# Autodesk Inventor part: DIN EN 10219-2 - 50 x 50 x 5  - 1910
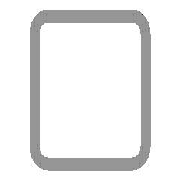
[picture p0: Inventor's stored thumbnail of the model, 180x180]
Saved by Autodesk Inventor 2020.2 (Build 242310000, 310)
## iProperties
IsCustomPart: 1
_CCFamilyMember: 16
_CCFamilyDisplayName: DIN EN 10219-2 (Quadratisches Hohlprofil - Kaltgeformt) - Kaltgeformte, geschweißte Baustahl-Hohlprofile aus unlegiertem Feinkorn-Baustahl
_FrameMemberDoc: Frame Member File
_Version: 15.0.0
_GetPNFromCC: 1
Created: 2019-01
Part Number: DIN EN 10219-2 - 50 x 50 x 5  - 1910
Material: Stahl, weich
Description: Kaltgeformte, geschweißte Baustahl-Hohlprofile aus unlegiertem Feinkorn-Baustahl
Document SubType Name: Modeling
Standard: DIN
Designer: lutzd
Standard Revision: 2006-07
Standards Organization: DIN
Language: de-DE
Size Designation: 50 x 50 x 5
Categories: <MemberInstance><Categories><Category DisplayName="Profile" InternalName="089c4875-fa83-4c05-b084-43b9cc11f5ed" Mnemonic="GRDR"><CategoryParameter DisplayName="
Stock Number: 50 x 50 x 5
Mass: 12515.2 g
Surface Area: 6404.35 cm^2
Volume: 1594.3 cm^3
Density: 7.85 g/cm^3
Appearance: Semi-Polished(8)
G_L: 1910,000 mm
G_W: 50,000 mm
G_H: 50,000 mm
DocNumber: ADSK-014383
Folder: .
Mass: 12,515 kg
VLT_Material: Stahl, weich
+C44415D3-DE04-4AD7-8A43-A2E09D2D25DA+SCHNITTDETAIL1: Schnittwinkel 90,00 grd
+0C2ABF72-8B65-4217-8014-3100D4A5692D+SCHNITTDETAIL2: Schnittwinkel 90,00 grd
Dimensions: 50x50x1910 mm
Title: Profil-Bauteil
Author: lutzd
Revision Number: -
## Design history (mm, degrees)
node "Startebene"
node "Endebene"
sketch "Skizze"
  geometry: L1 (-25, -15)-(-25, 15); L2 (-15, 25)-(15, 25); L3 (25, 15)-(25, -15); L4 (15, -25)-(-15, -25); L5 (-15, 20)-(15, 20); L6 (20, 15)-(20, -15); L7 (15, -20)-(-15, -20); L8 (-20, -15)-(-20, 15); L9 (0, 37.899)-(0, -37.899) reference; L10 (-37.899, 0)-(37.899, 0) reference; A1 r 10 centre (-15, -15) between (-25, -15) and (-15, -25); A2 r 10 centre (-15, 15) between (-15, 25) and (-25, 15); A3 r 10 centre (15, 15) between (25, 15) and (15, 25); A4 r 10 centre (15, -15) between (15, -25) and (25, -15); A5 r 5 centre (-15, 15) between (-15, 20) and (-20, 15); A6 r 5 centre (15, 15) between (20, 15) and (15, 20); A7 r 5 centre (15, -15) between (15, -20) and (20, -15); A8 r 5 centre (-15, -15) between (-20, -15) and (-15, -20)
  constraints: 16 end point, 16 point on circle, 8 centre point, 8 tangent, 4 parallel, 3 equal radius, 2 perpendicular, 7 other
  dimensions: "d7" = 10 radius of A1 (= G_IR); "d10" = 50 distance between parallel lines of L2 L4 (= G_H); "d11" = 50 distance between parallel lines of L1 L3 (= G_W); "d12" = 5 distance between parallel lines of L3 L6 (= G_T); "d15" = 25 distance between parallel lines of L2 L10 (= 0.5 x d10); "d16" = 25 distance between parallel lines of L9 L3 (= 0.5 x d11)
extrude "Körper" new body sketch "Skizze" stored distance "d3" = 1910 (= G_L); taper "d4" = 0 deg
node "Driven Length"
  sketch "Sketch3"
    geometry: L1 (0, 0)-(10, 0) reference
    constraints: 2 end point, 1 horizontal
  workplane "Work Plane3"
  sketch "Sketch4"
    geometry: L1 (-2, 50)-(12, 50) reference; L2 (-2, 1960)-(12, 1960) reference
    dimensions: "d18" = 1910 distance between parallel lines of L1 L2 (derived)
workplane "Arbeitsebene4"
feature "Trennen1"
workplane "Arbeitsebene5"
feature "Trennen2"
sketch "Skizze5"
  geometry: L1 (30, 0)-(0, 0) reference; L2 (15, 0)-(15, 200); 3 further points
  constraints: 4 end point, 1 coincident, 1 horizontal, 1 midpoint, 1 point on line, 1 vertical, 2 other
  dimensions: "d19" = 70 distance of point (15, 130) point (15, 200); "d20" = 200 distance of L2.start L2.end
hole "Bohrung1" sketch "Skizze5" at (15, 200), (15, 130) diameter "d21" = 6.647; stored, may be unused: countersink angle "d25" = 90 deg, drill point angle "d27" = 118 deg; dims "d22" = 16, "d23" = 4, "d24" = 2, "d26" = 8
sketch "Skizze6"
  geometry: L1 (0, 1910)-(-30, 1910) reference; L2 (-15, 1910)-(-15, 532); 5 further points
  constraints: 4 end point, 3 point on line, 1 coincident, 1 horizontal, 1 midpoint, 1 vertical, 2 other
  dimensions: "d28" = 90 distance of point (-15, 1395.5) point (-15, 1485.5); "d29" = 424.5 distance from line of L1 point (-15, 1485.5); "d30" = 863.5 distance of point (-15, 622) point (-15, 1485.5); "d31" = 90 distance of point (-15, 622) point (-15, 532)
hole "Bohrung2" sketch "Skizze6" at (-15, 532), (-15, 622), (-15, 1395.5), (-15, 1485.5) diameter "d32" = 6.647; stored, may be unused: countersink angle "d36" = 90 deg, drill point angle "d38" = 118 deg; dims "d33" = 16, "d34" = 4, "d35" = 2, "d37" = 8
body "Solid1"
other parameters: "G_W" = 50 [user parameter; used in 1 equation term], "G_H" = 50 [user parameter; used in 1 equation term], "G_T" = 5 [user parameter; used in 1 equation term], "G_IR" = 10 [user parameter; used in 1 equation term], "G_L" = 1910 (= d18) [user parameter; used in 1 equation term], "d17" = 90 deg
